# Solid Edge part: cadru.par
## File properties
Author: user
Template: Normal.par
Last saved by: Ionut
Revision: 7
Application: Solid Edge
Accuracy: 0.99
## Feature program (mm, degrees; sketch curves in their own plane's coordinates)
sketch for "unnamed Protrusion 1" plane through (0, 0, 0) normal (0, -1, 0) x-axis (1, 0, 0)
  line (-86.7389, -50) -> (-86.7389, 5)
  line (-76.7389, -50) -> (-86.7389, -50)
  line (-76.7389, -50) -> (-76.7389, -5)
  line (-76.7389, -5) -> (53.2611, -5)
  line (53.2611, -5) -> (53.2611, 50)
  line (43.2611, 50) -> (53.2611, 50)
  line (43.2611, 5) -> (43.2611, 50)
  line (-86.7389, 5) -> (43.2611, 5)
extrude "unnamed Protrusion 1" add finite 10 symmetric
sketch for "ExtrudedProtrusion_3" plane through (-31.7389, -5, 10) normal (0, -1, 0) x-axis (1, 0, 0)
  circle centre (80, 35) radius 3
extrude "ExtrudedProtrusion_3" add finite 1 along +normal
sketch for "ExtrudedProtrusion_4" plane through (18.2611, -6, 45) normal (0, -1, 0) x-axis (1, 0, 0)
  circle centre (30, 0) radius 1.5
extrude "ExtrudedProtrusion_4" add finite 6 along +normal
sketch for "ExtrudedProtrusion_5" plane through (-36.7389, 0, 5) normal (0, 0, 1) x-axis (1, 0, 0)
  circle centre (-45.7307, 0) radius 2
extrude "ExtrudedProtrusion_5" add finite 7 along +normal
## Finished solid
Body 1: solid body, 16 faces, 30 edges, 16 vertices.
  Faces by surface: plane 13, cylinder 3
  Edges by curve: line 24, circle 6
Bounding box of the edges (mm): 140.000 x 17.000 x 100.000, from (-86.7389, -12, -50) to (53.2611, 5, 50).
Cylindrical faces by radius (mm): R1.5 x1, R2 x1, R3 x1
Planar faces by outward normal: +x 2, +y 1, +z 3, -x 2, -y 3, -z 2
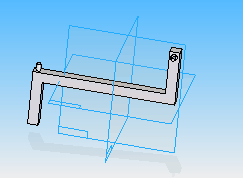
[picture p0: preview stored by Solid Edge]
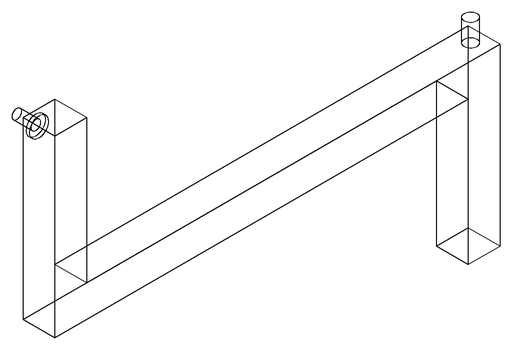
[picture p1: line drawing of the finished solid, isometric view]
